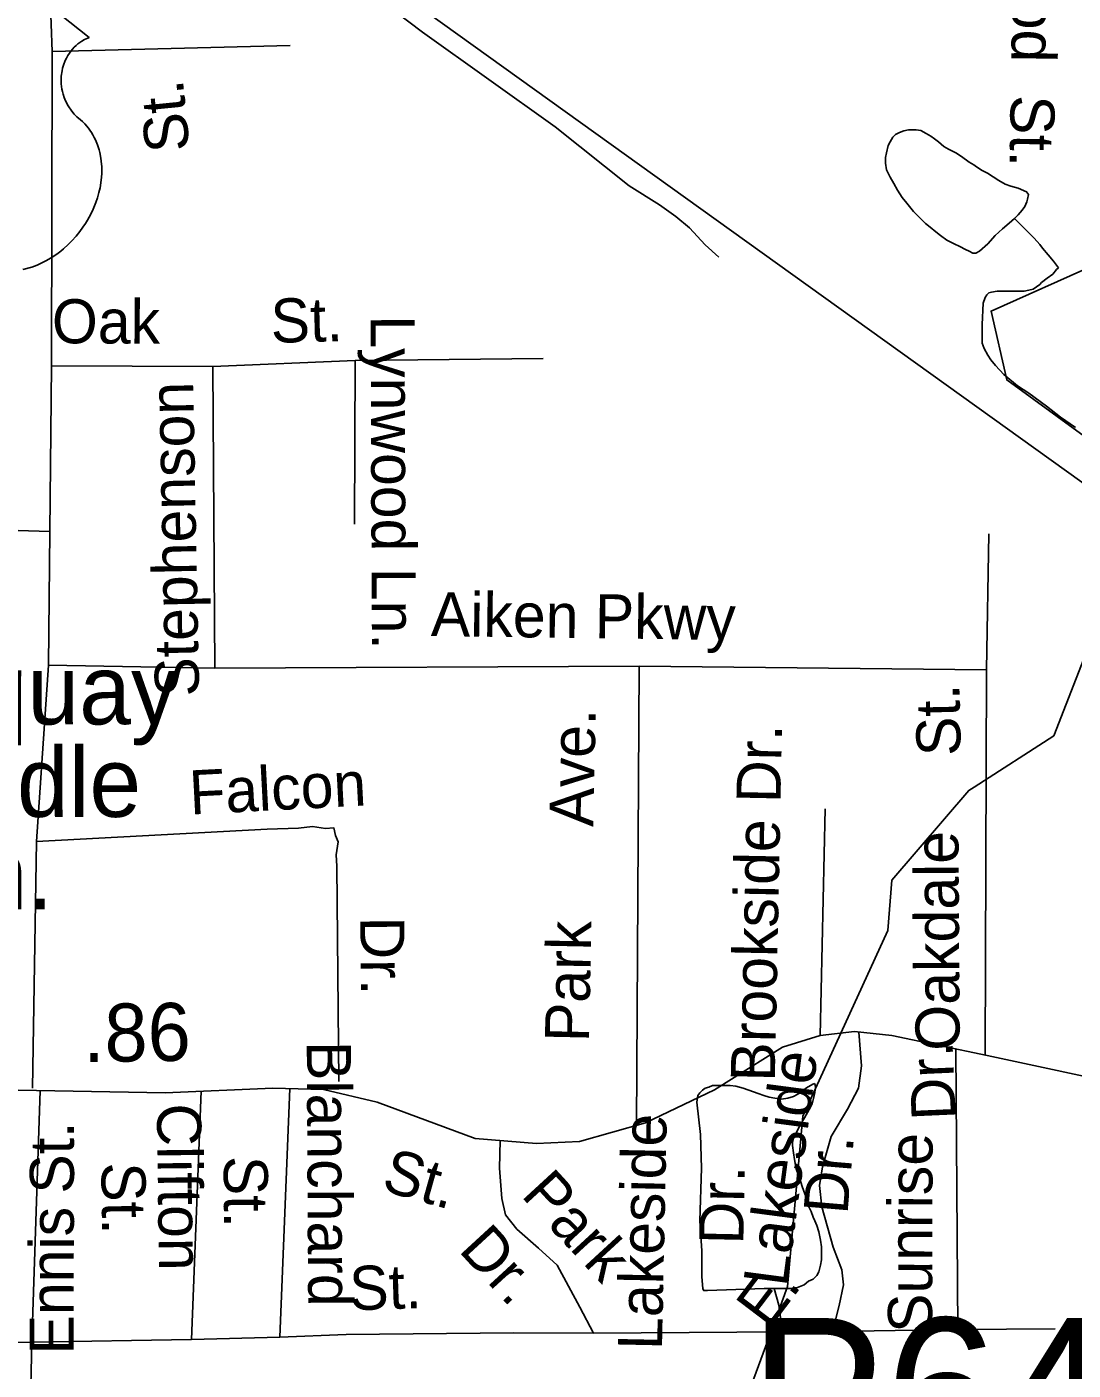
# Model space of a CAD drawing. Extents: x 2001466 to 2224147, y 644118 to 847247.
# Drawn here: x 2061470 to 2063724, y 667039 to 669932 of the extents above; entities that cross this region are included whole.
import ezdxf

# ---------------------------------------------------------------- set-up
doc = ezdxf.new("R2010")
doc.units = 0
for name, color, linetype in [('Exist Cultural Educational Facility Elementary Label', 7, 'Continuous'), ('Exist Hydrographic Misc Water Feature', 7, 'Continuous'), ('Exist Railroad Mainline', 7, 'Continuous'), ('Exist Road Non-System Type 51', 7, 'Continuous'), ('Exist Road Non-System Type 51 Label', 7, 'Continuous'), ('Exist Road Primary US Shield CELL', 7, 'Continuous'), ('Exist Road Secondary Mileage Hundredths English Label', 7, 'Continuous'), ('Exist Road Secondary Structure Pipe Number Label', 7, 'Continuous'), ('Exist Road Secondary Type 51 Attributed', 7, 'Continuous'), ('Exist Road Secondary Type 51 Label', 7, 'Continuous')]:
    doc.layers.add(name, color=color, linetype=linetype)

msp = doc.modelspace()

# ---------------------------------------------------------------- linework, layer by layer
at = {"layer": 'Exist Hydrographic Misc Water Feature'}
for points in [[(2063598, 669519.2), (2063606, 669527.2), (2063614, 669537.2), (2063620, 669545.3), (2063624.1, 669555.3), (2063626.1, 669561.3), (2063628, 669571.3), (2063623.9, 669577.3), (2063606, 669585.2), (2063590, 669589.2), (2063577.9, 669593.2), (2063564, 669601.2), (2063551.9, 669609.1), (2063540, 669617.1), (2063527.9, 669623.1), (2063516, 669631.1), (2063509.9, 669635.1), (2063500, 669641), (2063483.8, 669653), (2063471.7, 669661), (2063455.7, 669668.9), (2063445.9, 669674.9), (2063433.8, 669684.9), (2063425.8, 669690.9), (2063417.8, 669696.9), (2063407.7, 669702.9), (2063395.8, 669708.8), (2063385.8, 669710.8), (2063377.8, 669710.8), (2063369.8, 669710.8), (2063359.8, 669708.7), (2063349.9, 669704.7), (2063341.7, 669700.7), (2063335.8, 669694.7), (2063329.8, 669684.7), (2063325.7, 669676.7), (2063322, 669660.7), (2063320, 669650.7), (2063320, 669638.7), (2063322, 669624.6), (2063330, 669608.8), (2063338, 669594.7), (2063346, 669580.7), (2063356.1, 669564.8), (2063366.1, 669552.8), (2063380.1, 669534.8), (2063396.3, 669518.8), (2063406.1, 669508.8), (2063416.1, 669500.9), (2063428.2, 669490.9), (2063438.1, 669482.9), (2063452.2, 669473), (2063468.2, 669465), (2063480.1, 669459.1), (2063492.2, 669453.1), (2063500.2, 669449.1), (2063508.2, 669445.1), (2063514.2, 669445.1), (2063522.2, 669449.1), (2063540.2, 669465.1), (2063556.2, 669483.2), (2063572.2, 669497.2), (2063586.1, 669509.3), (2063598, 669519.2)], [(2063598, 669519.2), (2063624.3, 669493.3), (2063640.3, 669477.3), (2063652.2, 669463.4), (2063658.1, 669455.4), (2063670.2, 669441.4), (2063682.1, 669427.4), (2063692.4, 669413.4)], [(2063692.4, 669413.4), (2063688.3, 669409.4), (2063680.3, 669399.4), (2063668.4, 669391.3), (2063656.3, 669381.4), (2063652.4, 669377.4), (2063638.2, 669367.4), (2063628.4, 669365.3), (2063618.3, 669363.3), (2063606.2, 669363.3), (2063598.2, 669363.3), (2063586.3, 669363.3), (2063574.4, 669363.3), (2063560.5, 669363.2), (2063548.4, 669361.2), (2063542.5, 669359.2), (2063538.4, 669355.2), (2063534.5, 669349.2), (2063530.4, 669337.2), (2063528.5, 669291.2), (2063528.5, 669275.2), (2063528.5, 669259.2), (2063528.5, 669251.2), (2063532.6, 669239.2), (2063540.6, 669225.2), (2063546.8, 669215.2), (2063556.6, 669203.2), (2063574.7, 669183.2), (2063604.6, 669159.3), (2063628.8, 669143.4), (2063666.7, 669115.4), (2063696.9, 669091.5), (2063728.9, 669069.6)], [(2064224.2, 669184), (2064214.2, 669080.2), (2064148.2, 668996.2), (2064031.3, 669021.5), (2063906.2, 669122.5), (2063772.3, 669420.5), (2063547.4, 669320.1), (2063581.2, 669171.8), (2064073.3, 668814), (2064073.3, 668781.2)], [(2063510.6, 668294.9), (2063682.3, 668405.3), (2063757.4, 668597.3), (2063914.5, 668653.9)], [(2063084.3, 667151.8), (2063109.2, 667219.4), (2063142.2, 667586.2), (2063325.3, 667986), (2063333.3, 668094.1), (2063499.2, 668287.6), (2063510.6, 668294.9)], [(2063167.4, 667656.8), (2063163.5, 667654.8), (2063149.6, 667646.8), (2063135.6, 667636.7), (2063129.7, 667632.7), (2063121.7, 667628.7), (2063109.6, 667624.7), (2063095.7, 667622.7), (2063081.7, 667624.7), (2063069.6, 667626.7), (2063057.7, 667630.6), (2063045.6, 667634.6), (2063035.6, 667638.6), (2063013.6, 667646.6), (2062997.6, 667650.5), (2062985.5, 667652.5), (2062975.7, 667652.5), (2062965.6, 667652.4), (2062947.6, 667652.4), (2062939.6, 667648.4), (2062931.6, 667646.4), (2062925.7, 667642.4), (2062919.7, 667636.4), (2062915.6, 667630.4), (2062913.6, 667616.4), (2062921.8, 667546.3), (2062923.8, 667474.4), (2062920.1, 667360.4), (2062924.2, 667296.4), (2062924.4, 667240.5), (2062926.3, 667214.5), (2062928.3, 667210.5), (2062936.3, 667210.5), (2063058.3, 667214.7), (2063080.3, 667214.7)], [(2063080.3, 667214.7), (2063096.3, 667214.8), (2063116.4, 667214.8), (2063130.3, 667216.9), (2063144.5, 667222.9), (2063154.3, 667230.9), (2063164.3, 667234.9), (2063172.3, 667242.9), (2063176.2, 667250.9), (2063180.3, 667264.9), (2063182.2, 667276.9), (2063182.2, 667286.9), (2063182.2, 667304.9), (2063180.1, 667318.9), (2063176, 667336.9), (2063172.1, 667350.9), (2063168, 667360.9), (2063164.1, 667368.9), (2063160, 667380.9), (2063152, 667396.9), (2063147.9, 667414.9), (2063144, 667424.8), (2063139.9, 667436.8), (2063135.8, 667448.8), (2063131.9, 667460.8), (2063127.8, 667472.8), (2063125.8, 667480.8), (2063123.9, 667492.8), (2063121.9, 667506.8), (2063119.8, 667522.7), (2063119.8, 667530.8), (2063121.7, 667538.8), (2063125.8, 667546.7), (2063129.7, 667554.8), (2063135.8, 667566.8), (2063145.7, 667582.8), (2063155.5, 667600.8), (2063161.7, 667612.8), (2063165.6, 667626.8), (2063167.6, 667636.8), (2063169.5, 667648.8), (2063167.4, 667656.8)], [(2063080.3, 667214.7), (2063090.3, 667178.8), (2063094.4, 667146.8), (2063096.5, 667120.8), (2063094.6, 667100.8), (2063094.6, 667084.8), (2063092.6, 667066.8), (2063090.5, 667046.8), (2063086.8, 667024.8), (2063078.8, 667002.8), (2063070.6, 666988.8), (2063068.8, 666980.8), (2063060.8, 666972.8), (2063054.8, 666960.7), (2063046.8, 666950.7), (2063040.9, 666942.7), (2063030.9, 666928.7), (2063024.9, 666922.7), (2063018.8, 666914.7), (2063007.1, 666902.7), (2063000.9, 666898.7), (2062995, 666892.7)], [(2062831.5, 666709), (2062902.3, 666787.3), (2063018.1, 666971.9), (2063084.3, 667151.8)]]:
    msp.add_lwpolyline(points, dxfattribs=at)
at = {"layer": 'Exist Railroad Mainline'}
msp.add_lwpolyline([(2061940.4, 670256.2), (2062333, 669963.3), (2064007.3, 668762.3), (2064227.5, 668602.6), (2064343.6, 668518.5), (2064545.6, 668362.6), (2064637.6, 668286.5), (2064715.6, 668206.6), (2064728.2, 668192.2), (2068257.7, 663344.7), (2068669, 662748.9)], dxfattribs=at)
at = {"layer": 'Exist Road Non-System Type 51'}
for p, q in [((2061524.6, 669879.1), (2061513, 670249.3)), ((2061523.3, 669201.9), (2061524.6, 669879.1)), ((2061524.6, 669879.1), (2062037.8, 669892.4)), ((2061519.8, 668845.2), (2061523.3, 669201.9)), ((2061523.3, 669201.9), (2061870.7, 669200.6)), ((2061870.7, 669200.6), (2062177.8, 669214)), ((2061870.7, 669200.6), (2061875.3, 668551)), ((2062177.8, 669214), (2062176, 668861.2)), ((2062177.8, 669214), (2062582.7, 669218)), ((2061099.1, 668860), (2061519.8, 668845.2)), ((2061517.1, 668557.7), (2061519.8, 668845.2)), ((2063537.5, 668547.5), (2063542.8, 668840.4)), ((2061491.2, 668178), (2061517.1, 668557.7)), ((2061517.1, 668557.7), (2061875.3, 668551)), ((2061875.3, 668551), (2062789.1, 668555.5)), ((2062783.6, 667566.2), (2062789.1, 668555.5)), ((2062789.1, 668555.5), (2063537.5, 668547.5)), ((2063537.5, 668547.5), (2063534.7, 667717.4)), ((2063179.5, 667759.8), (2063190, 668248)), ((2061482.4, 667646.2), (2061491.2, 668178)), ((2061481.3, 667099.6), (2061473.8, 666757.3))]:
    msp.add_line(p, q, dxfattribs=at)
for points in [[(2061867.9, 670256.1), (2062078.5, 670106.1), (2062322.7, 669921.2), (2062608.6, 669717.3), (2062768, 669590.1), (2062833.1, 669548.8), (2062868.6, 669524.1), (2062898.1, 669499.5), (2062931.4, 669462.8), (2062960.8, 669436.2)], [(2062142.7, 667660.8), (2062138.1, 668124.9), (2062136.6, 668148.9), (2062141.2, 668176.8), (2062135.5, 668190.9), (2062131.8, 668207), (2062113.8, 668205.4), (2062085.9, 668209.9), (2062055.8, 668206.6), (2061987.7, 668203.9), (2061491.2, 668178)], [(2063205.8, 667122.4), (2063220.5, 667178.5), (2063229.8, 667222.7), (2063225.8, 667254.8), (2063207.1, 667304.2), (2063183.1, 667391.1), (2063177.7, 667436.6), (2063184.4, 667476.7), (2063203.1, 667542.2), (2063237.9, 667601.1), (2063261.9, 667646.5), (2063268.6, 667694.7), (2063262.3, 667767.3)], [(2063475.7, 667126.4), (2063471.7, 667730.7)], [(2061481.3, 667099.6), (2061499.2, 667641.4)], [(2061825.3, 667105), (2061846, 667639.7)], [(2062015.1, 667110.3), (2062036.9, 667645.7)], [(2062691.3, 667118.4), (2062661.9, 667174.5), (2062612.4, 667265.5), (2062572.3, 667301.6), (2062525.6, 667343), (2062501.5, 667373.8), (2062493.5, 667408.5), (2062488.2, 667474.1), (2062489.8, 667533.6)], [(2062015.1, 667110.3), (2062158.1, 667115.7), (2062518.9, 667119.7), (2062691.3, 667118.4)], [(2062691.3, 667118.4), (2063205.8, 667122.4)], [(2063205.8, 667122.4), (2063475.7, 667126.4)], [(2063475.7, 667126.4), (2063685.6, 667127.7)], [(2060962, 667093), (2061481.3, 667099.6)], [(2061481.3, 667099.6), (2061825.3, 667105)], [(2061825.3, 667105), (2062015.1, 667110.3)]]:
    msp.add_lwpolyline(points, dxfattribs=at)
at = {"layer": 'Exist Road Primary US Shield CELL'}
msp.add_lwpolyline([(2061475.9, 670011.9), (2061604.5, 669909.5), (2061601.5, 669908.3), (2061594.5, 669904.9), (2061589, 669901.6), (2061580.1, 669895.4), (2061576.3, 669892), (2061572.5, 669888.4), (2061569, 669884.6), (2061565.9, 669881), (2061562.2, 669875.9), (2061558.9, 669870.7), (2061555.6, 669865), (2061553.2, 669860.1), (2061549.3, 669849.7), (2061547.4, 669843.2), (2061546.2, 669837.6), (2061544.6, 669826.2), (2061544.3, 669820.7), (2061544.3, 669815.3), (2061544.6, 669809.6), (2061545.1, 669804.1), (2061546.1, 669798.4), (2061547, 669793.4), (2061548.6, 669787.3), (2061550.9, 669780.1), (2061553.7, 669773.2), (2061559.6, 669762), (2061567.1, 669750.6), (2061572.5, 669744.3), (2061577.8, 669738.8), (2061585.8, 669732.1), (2061590.1, 669728.3), (2061595, 669723.4), (2061603, 669714), (2061606.3, 669709.6), (2061609.6, 669704.7), (2061612.7, 669699.6), (2061615.7, 669694.1), (2061618.1, 669689.3), (2061622.6, 669678.3), (2061625.9, 669667.6), (2061627.5, 669662), (2061629.9, 669649.3), (2061630.8, 669643.1), (2061631.8, 669630.8), (2061631.8, 669615.9), (2061630.7, 669601.8), (2061628, 669585.3), (2061625.8, 669575.4), (2061622.4, 669563.9), (2061619.1, 669554), (2061613.3, 669539.3), (2061608.1, 669528.7), (2061601.3, 669516.2), (2061596.7, 669508.7), (2061591.3, 669500.6), (2061584.5, 669491.4), (2061576.6, 669481.5), (2061567.1, 669471.1), (2061559.5, 669463.4), (2061549.4, 669454.4), (2061543.4, 669449.4), (2061534.7, 669442.9), (2061522.8, 669435), (2061511.1, 669428.2), (2061501.2, 669423.1), (2061492.4, 669419.3), (2061481, 669415), (2061462, 669409.8)], dxfattribs=at)
at = {"layer": 'Exist Road Secondary Type 51 Attributed'}
msp.add_lwpolyline([(2059511, 667649), (2060002.9, 667648.9), (2060717, 667648.9), (2061331.8, 667644.6), (2061768.3, 667636.2), (2062000.5, 667646.7), (2062109.2, 667643.6), (2062225.3, 667616.1), (2062435.9, 667538), (2062567.9, 667527.4), (2062660.7, 667531.6), (2062803.2, 667571.8), (2062951.5, 667642.5), (2063098.3, 667734.4), (2063179.5, 667759.8), (2063253.4, 667768.2), (2063333.7, 667759.8), (2063539, 667716.5), (2063856.7, 667648.9), (2064013.9, 667620.3), (2064115.4, 667601.2)], dxfattribs=at)

# ---------------------------------------------------------------- texts
at = {"layer": 'Exist Cultural Educational Facility Elementary Label'}
for s, p in [('Fuquay', (2061125.9, 668429.9)), ('Middle', (2061125.9, 668230.7)), ('Sch.', (2061125.9, 668031.4))]:
    msp.add_text(s, height=150, dxfattribs=at).set_placement(p)
at = {"layer": 'Exist Road Non-System Type 51 Label'}
for s, rotation, p in [('Smithwood  St.', 269.0766, (2063601, 670484.8)), ('St.', 95.5966, (2061821.4, 669666.9)), ('Oak', 359.7094, (2061524.2, 669250.9)), (' St.', 1.459, (2061961.4, 669250.7)), ('Lynwood Ln.', 270.2227, (2062210.9, 669310.9)), ('Stephenson', 91.1203, (2061841.7, 668490.5)), ('Aiken Pkwy', 359.2413, (2062340.3, 668620.2)), (' St.', 91.1956, (2063483, 668327.4)), ('Ave.', 88.8338, (2062690.6, 668208.9)), ('Brookside Dr.', 88.8336, (2063081.5, 667659.9)), ('Falcon', 2.9881, (2061822.6, 668235.6)), ('Oakdale', 90.3403, (2063479.8, 667727.4)), ('Dr.', 270.5622, (2062188.4, 668015.6)), ('Park', 88.8338, (2062681.2, 667745)), ('Blanchard', 270.3246, (2062073.3, 667747.6)), ('Lakeside', 82.5041, (2063107.8, 667216.7)), ('Dr.', 92.5465, (2063471.6, 667579.4)), ('Clifton', 270.743, (2061750.4, 667612.9)), ('Lakeside', 88.8245, (2062838.4, 667082)), (' St.', 89.8945, (2061571.7, 667383.9)), ('Dr.', 85.1951, (2063237.9, 667373.1)), ('Sunrise', 89.8263, (2063420.1, 667119.2)), (' St.', 270.3246, (2061894.2, 667535.5)), (' St.', 270.743, (2061630.3, 667521.4)), ('Park ', 312.6078, (2062532.9, 667414.9)), ('Dr.', 88.8245, (2063013.6, 667309.2)), ('Ennis', 89.8945, (2061571.2, 667072.8)), ('Dr.', 312.6078, (2062398.2, 667296.6)), (' St.', 1.8767, (2062131.2, 667166.6)), ('E. ', 52.7723, (2063068.2, 667125.2))]:
    msp.add_text(s, height=95, rotation=rotation, dxfattribs=at).set_placement(p)
at = {"layer": 'Exist Road Secondary Mileage Hundredths English Label'}
msp.add_text('.86', height=125, rotation=0.767, dxfattribs=at).set_placement((2061591.8, 667702.5))
at = {"layer": 'Exist Road Secondary Structure Pipe Number Label'}
msp.add_text('P642', height=328.08, dxfattribs=at).set_placement((2063026.2, 666823.2))
at = {"layer": 'Exist Road Secondary Type 51 Label'}
msp.add_text('St.', height=95, rotation=344.173, dxfattribs=at).set_placement((2062231.4, 667427.1))

doc.saveas('drawing.dxf')
